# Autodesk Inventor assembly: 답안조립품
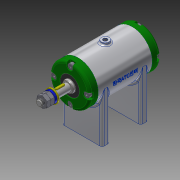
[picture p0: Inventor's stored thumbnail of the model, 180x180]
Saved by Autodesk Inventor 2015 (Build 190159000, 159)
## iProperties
Created: 2020-07
Part Number: 답안조립품
Document SubType Name: Assembly
Designer: LINEART-SSD.D4.16.04
Author: LINEART-SSD.D4.16.04
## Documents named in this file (15)
- C:\Users\LINEART-SSD.D4.16.04\Desktop\700706V1015\답안조립품.iam
- C:\Users\LINEART-SSD.D4.16.04\Desktop\700706V1015\본체.ipt
- C:\Users\LINEART-SSD.D4.16.04\Desktop\700706V1015\볼트 M6x8.ipt
- C:\Users\LINEART-SSD.D4.16.04\Desktop\700706V1015\와셔 6x11.5.ipt
- C:\Users\LINEART-SSD.D4.16.04\Desktop\700706V1015\뒤커버.ipt
- C:\Users\LINEART-SSD.D4.16.04\Desktop\700706V1015\볼트 M4x12.ipt
- C:\Users\LINEART-SSD.D4.16.04\Desktop\700706V1015\앞커버.ipt
- C:\Users\LINEART-SSD.D4.16.04\Desktop\700706V1015\베어링 6002.ipt
- C:\Users\LINEART-SSD.D4.16.04\Desktop\700706V1015\오일 실 15 25 7.ipt
- C:\Users\LINEART-SSD.D4.16.04\Desktop\700706V1015\축.ipt
- C:\Users\LINEART-SSD.D4.16.04\Desktop\700706V1015\V벨트풀리.ipt
- C:\Users\LINEART-SSD.D4.16.04\Desktop\700706V1015\키 3x3x12.ipt
- C:\Users\LINEART-SSD.D4.16.04\Desktop\700706V1015\너트 M8.ipt
- C:\Users\LINEART-SSD.D4.16.04\Desktop\700706V1015\스프링와셔 8.ipt
- C:\Users\LINEART-SSD.D4.16.04\Desktop\700706V1015\와셔 8x17.ipt
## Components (1 placed, 1 different names)
1. V벨트풀리:1
